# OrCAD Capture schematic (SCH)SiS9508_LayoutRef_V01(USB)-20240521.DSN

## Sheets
1 00_History: title: History; rev: V0.1; note: SiS9508_AP_V01
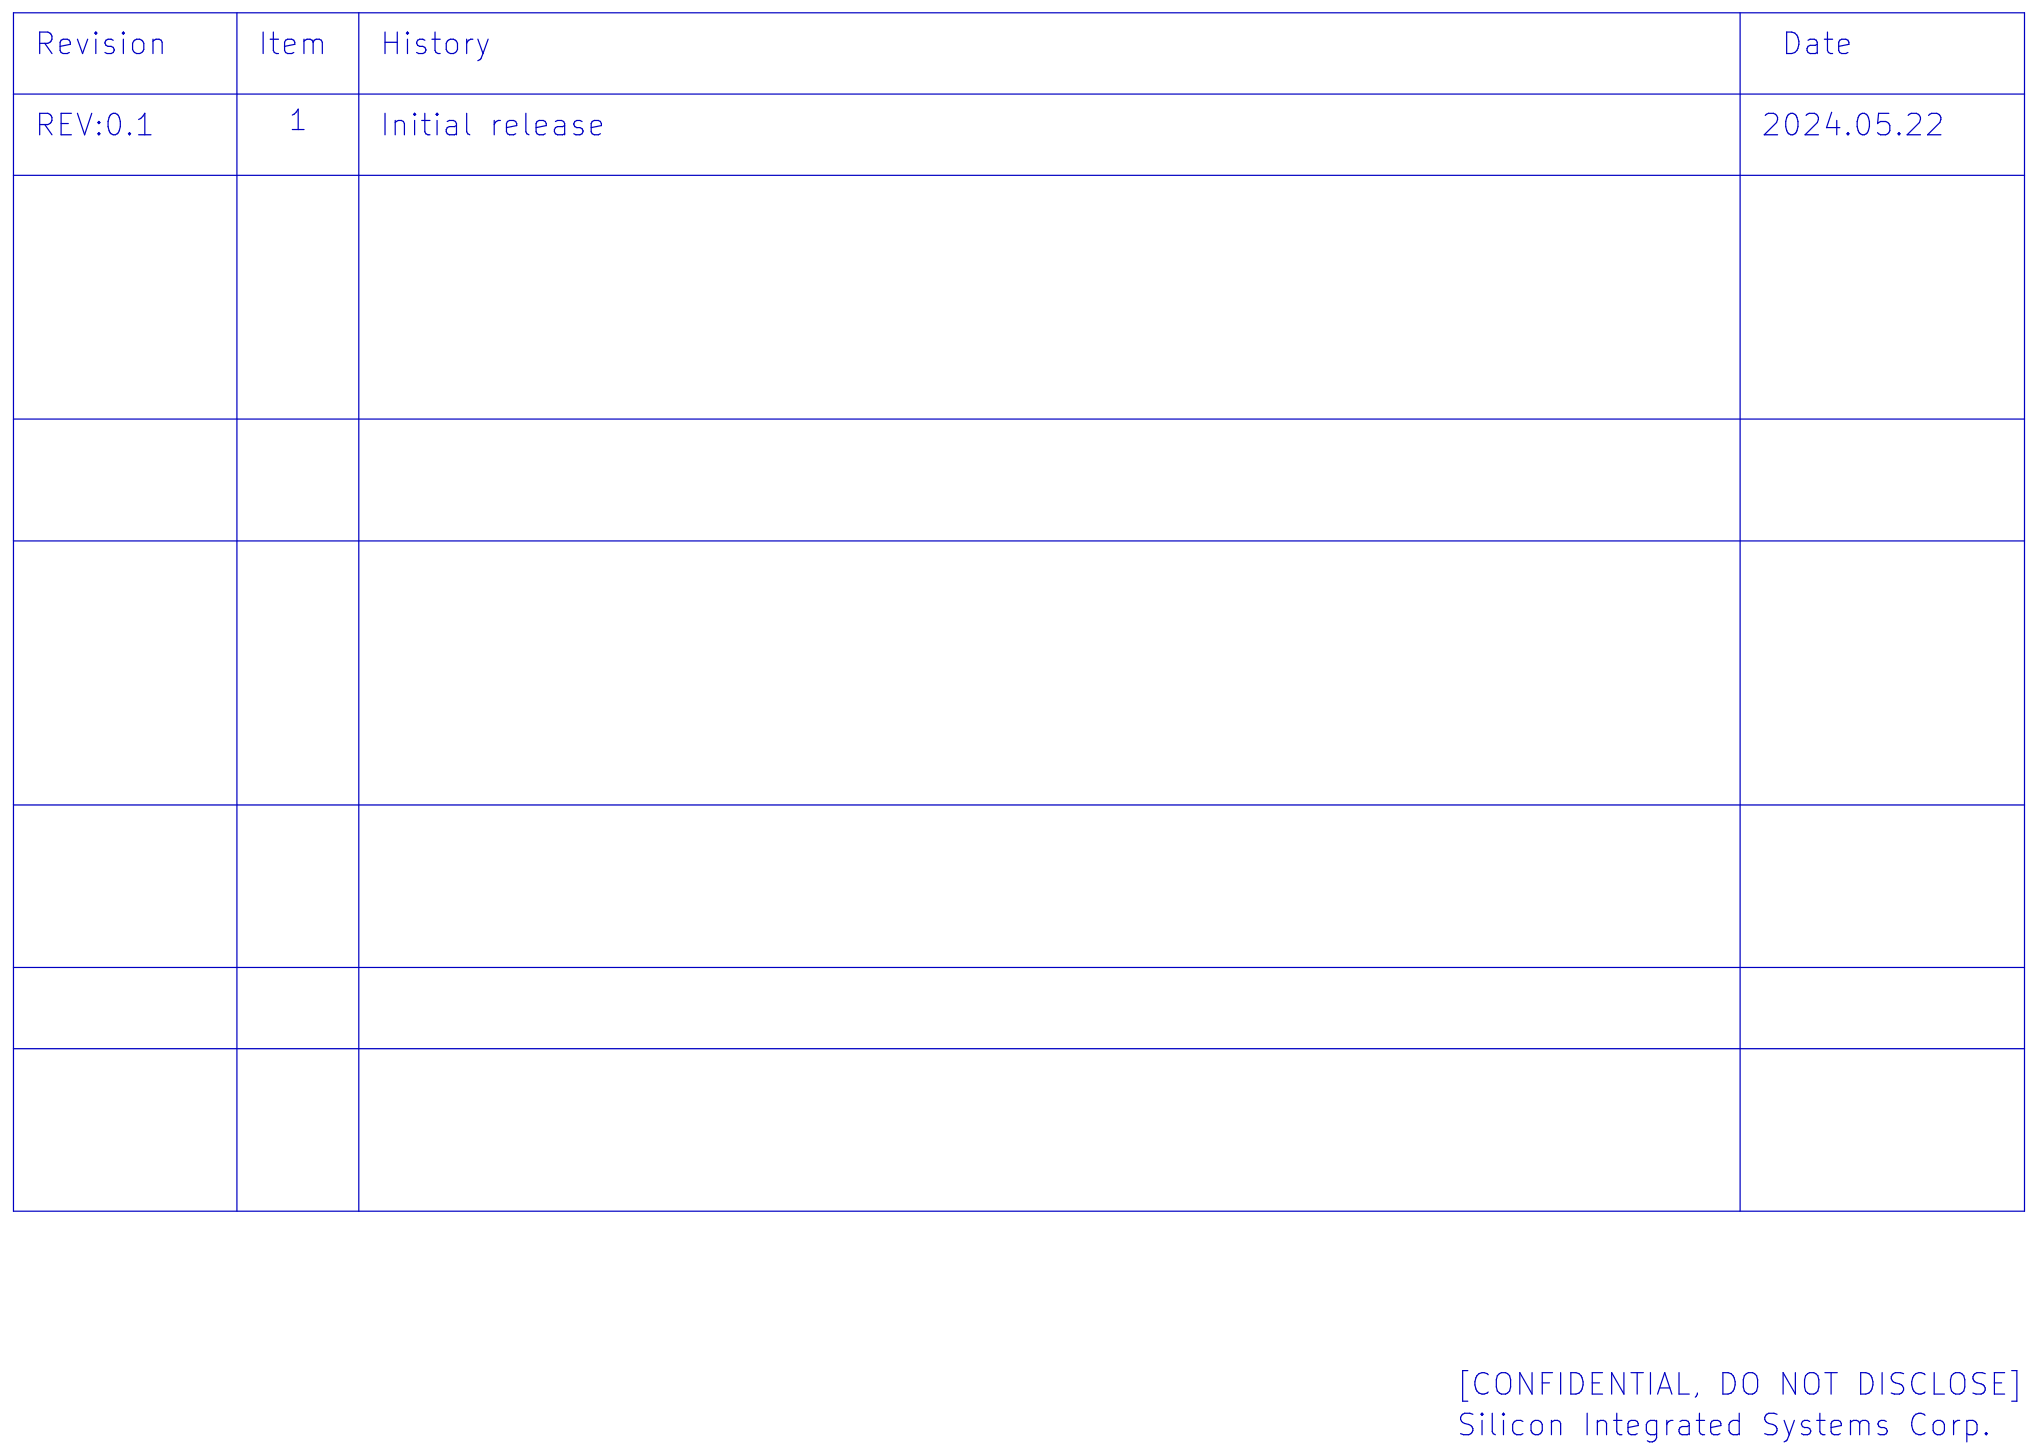
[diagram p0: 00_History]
2 01_SiS9508 - USB: size Custom; title: SiS9508; note: USB interface
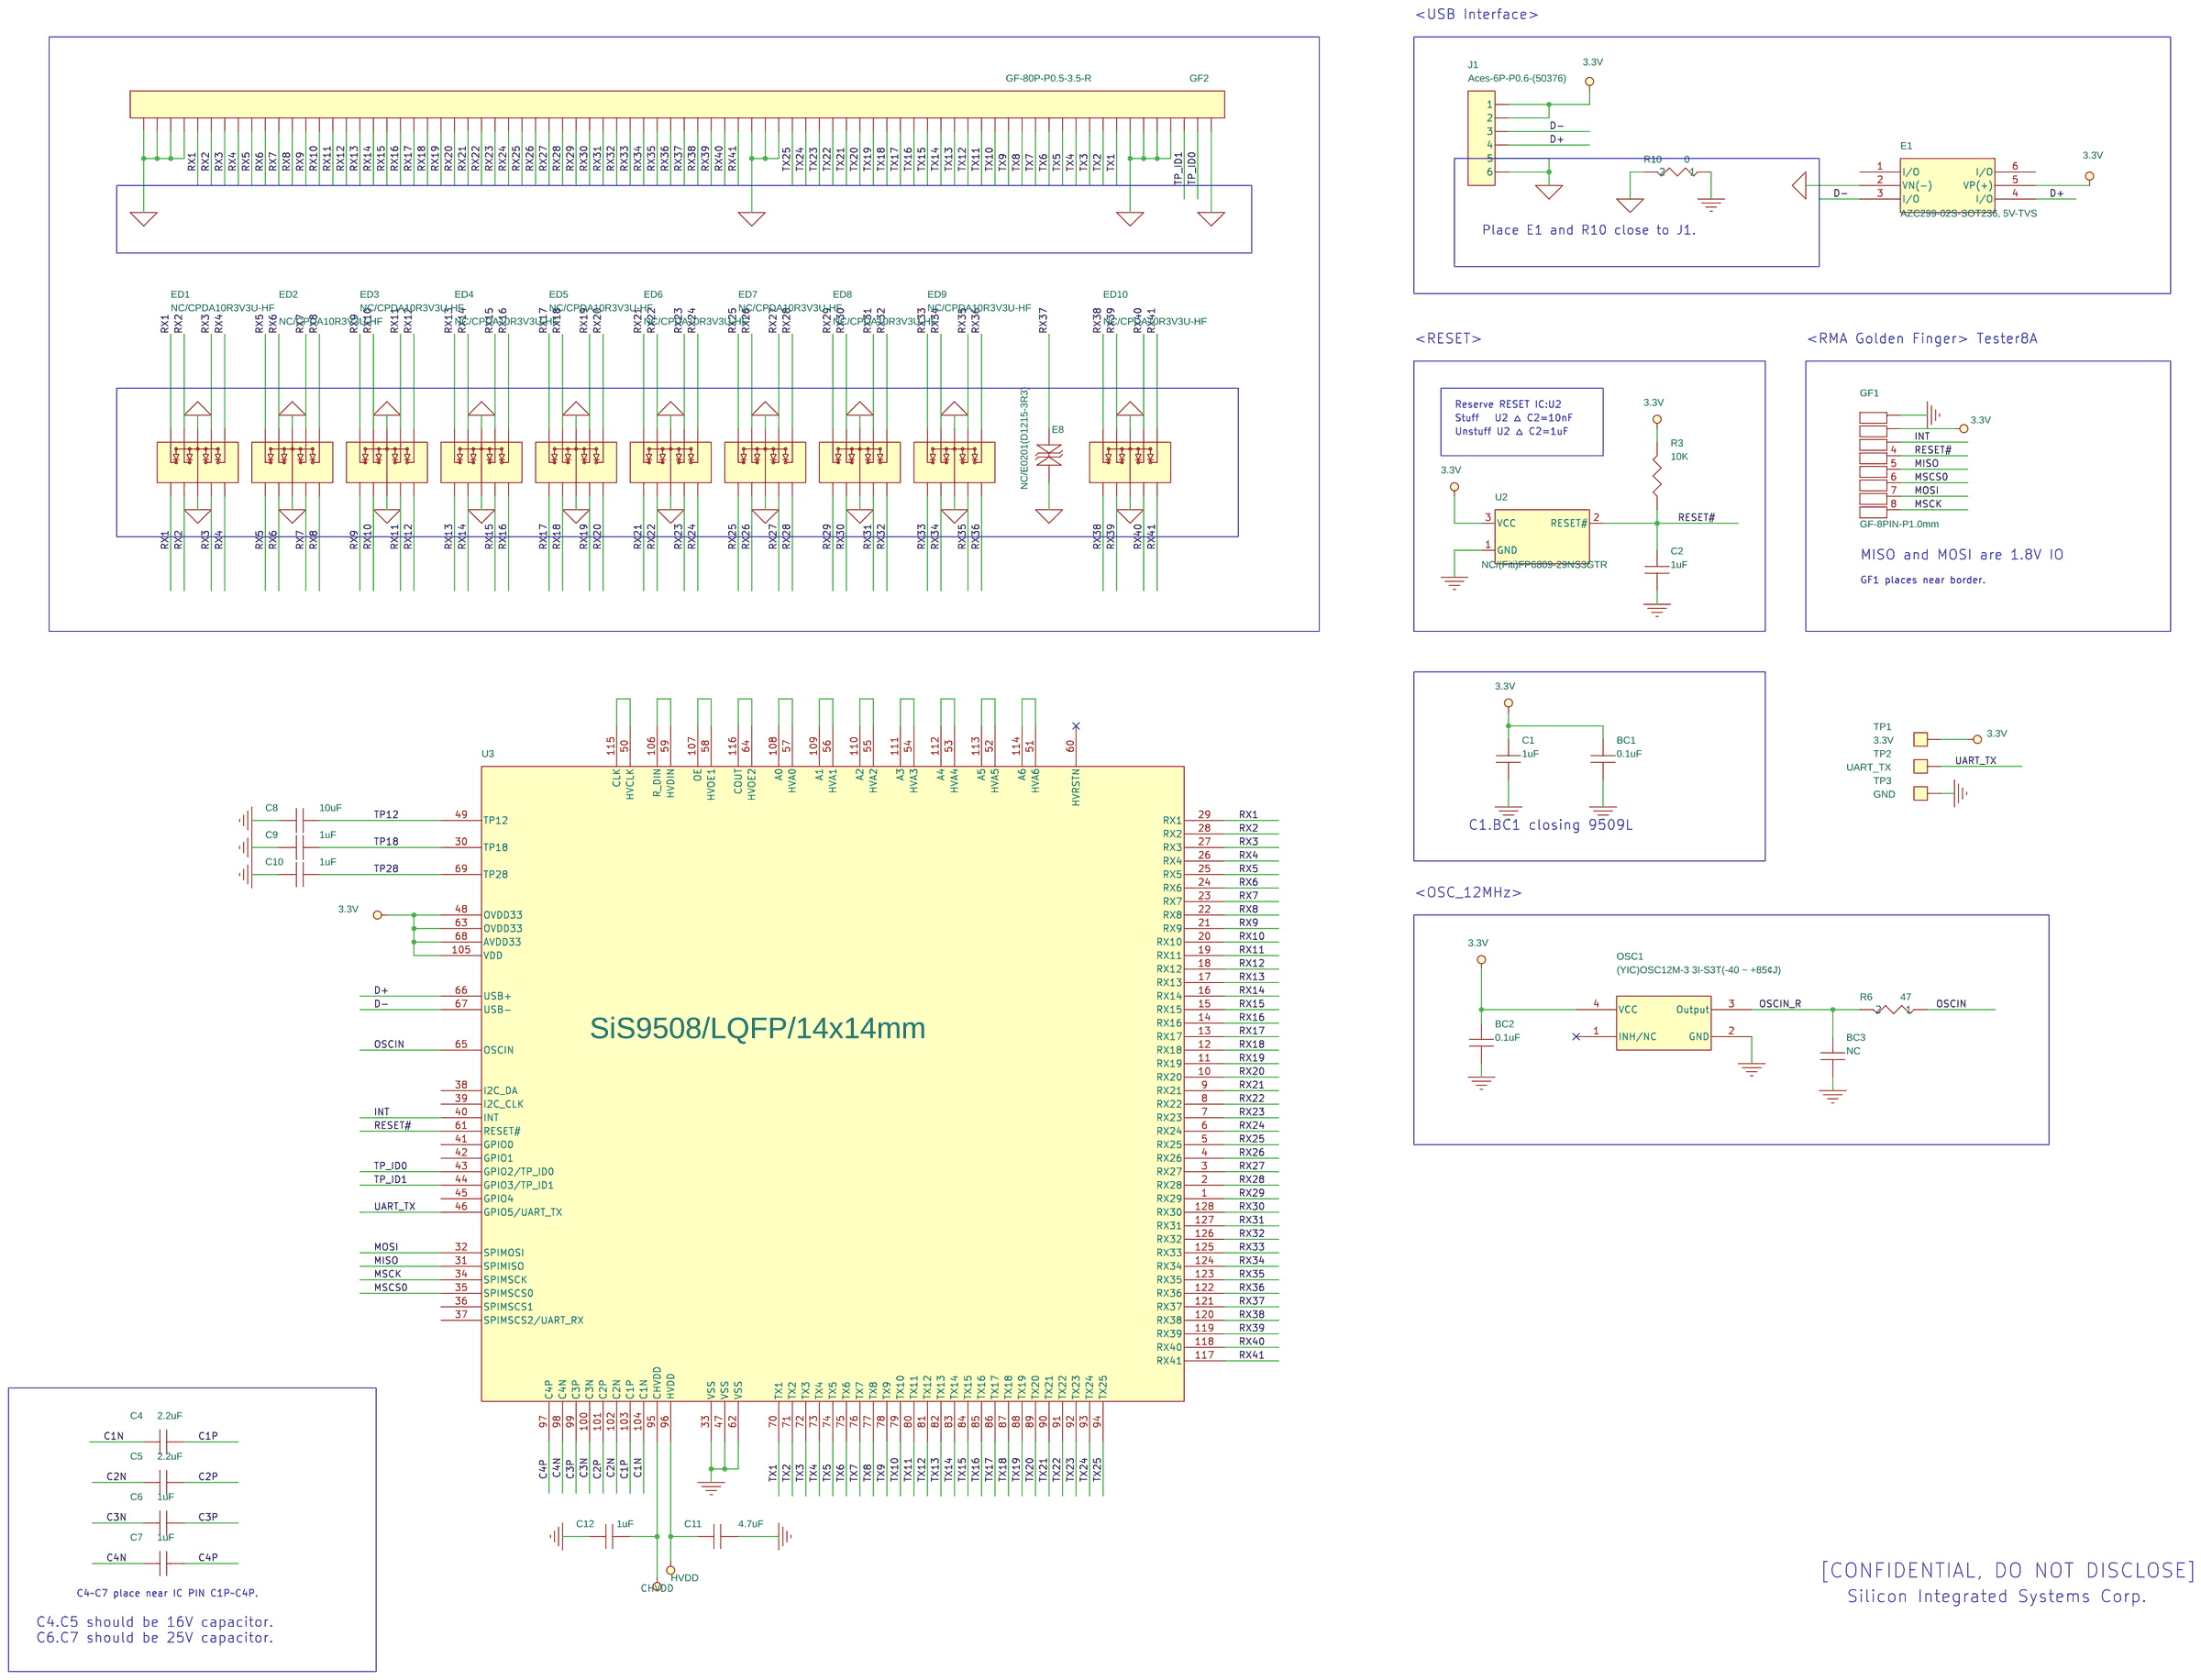
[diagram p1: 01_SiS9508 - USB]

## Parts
BC1  0.1uF  [C0402]
BC2  0.1uF  [C0402]
BC3  NC  [C0402]
C1  1uF  [C0402]
C2  1uF  [C0402]
C4  2.2uF  [C0402]
C5  2.2uF  [C0402]
C6  1uF  [C0402]
C7  1uF  [C0402]
C8  10uF  [C0402]
C9  1uF  [C0402]
C10  1uF  [C0402]
C11  4.7uF  [C0603]
C12  1uF  [C0402]
E1  AZC299-02S-SOT236, 5V-TVS  [E-SOT236L]
E8  NC/E0201(D1215-3R3)  [E0402]
ED1  NC/CPDA10R3V3U-HF  [E-CPDA10R3V3U-HF]
ED2  NC/CPDA10R3V3U-HF  [E-CPDA10R3V3U-HF]
ED3  NC/CPDA10R3V3U-HF  [E-CPDA10R3V3U-HF]
ED4  NC/CPDA10R3V3U-HF  [E-CPDA10R3V3U-HF]
ED5  NC/CPDA10R3V3U-HF  [E-CPDA10R3V3U-HF]
ED6  NC/CPDA10R3V3U-HF  [E-CPDA10R3V3U-HF]
ED7  NC/CPDA10R3V3U-HF  [E-CPDA10R3V3U-HF]
ED8  NC/CPDA10R3V3U-HF  [E-CPDA10R3V3U-HF]
ED9  NC/CPDA10R3V3U-HF  [E-CPDA10R3V3U-HF]
ED10  NC/CPDA10R3V3U-HF  [E-CPDA10R3V3U-HF]
GF1  GF-8PIN-P1.0mm  [GF-8-1.0-1.2]
GF2  GF-80P-P0.5-3.5-R  [GF-80P-P0.5-3.5-R]
J1  Aces-6P-P0.6-(50376)  [CON-6P-P0.6-0.8(50376)]
OSC1  (YIC)OSC12M-3 3I-S3T(-40 ~ +85¢J)  [OSC-4P-SCO-F391]
R3  10K  [R0402]
R6  47  [R0402]
R10  0  [R0402]
TP1  3.3V  [TP1.2]
TP2  UART_TX  [TP1.2]
TP3  GND  [TP1.2]
U2  NC/(Fiti)FP6809-29NS3GTR  [SOT-23/SC-70-3]
U3  SiS9508/LQFP/14x14mm  [(9508)LQFP128P-P0.4-1414-SOCKET.]

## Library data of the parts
BC1-BC3 C1 C2 C8-C10 C12 = C-NP_(C0402_6.3V)
C4-C7 C11 = CAP_NP
E1 = AME8822AEET330Z_(SOT23)_2
E8 = C-NP_(C0402_6_0.3V)
ED1-ED10 = ESD_3: Geometry.Height: 0.55mm
GF1 = GFinger-12P_(GF-12-0.5-2_0.0)
GF2 = CON-80P-P0.5(TF06L_50520_106C)
J1 = CON-5P-P2-3_0.3(DF3DZ-5P-2H)
OSC1 = OSC813500-SCO-F39_0
R3 = R_(R0402)
R6 = R
R10 = R_1
TP1-TP3 = TESTPOINT-SURFACE
U2 = AME8822AEET330Z_(SOT-23)_0
U3 = (9508B)LQFP128P-P0.4-1414

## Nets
3.3V: BC1.1 BC2.1 C1.1 E1.5(VP(+)) GF1.2 J1.1 J1.2 OSC1.4(VCC) R3.2 TP1.1 U2.3(VCC) U3.48(OVDD33) U3.63(OVDD33) U3.68(AVDD33) U3.105(VDD)
DGND: BC1.2 BC2.2 BC3.2 C1.2 C2.2 C8.2 C9.2 C10.2 C11.2 C12.1 GF1.1 OSC1.2(GND) R10.1 TP3.1 U2.1(GND) U3.33(VSS) U3.47(VSS) U3.62(VSS)
GND_SIGNAL: E1.2(VN(-)) E8.2 ED1.3 ED1.8 ED2.3 ED2.8 ED3.3 ED3.8 ED4.3 ED4.8 ED5.3 ED5.8 ED6.3 ED6.8 ED7.3 ED7.8 ED8.3 ED8.8 ED9.3 ED9.8 ED10.3 ED10.8 GF2.1 GF2.4 GF2.5 GF2.6 GF2.7 GF2.33 GF2.34 GF2.35 GF2.77 GF2.78 GF2.79 GF2.80 J1.5 J1.6 R10.2
C1N: C4.1 U3.104(C1N)
C1P: C4.2 U3.103(C1P)
C2N: C5.1 U3.102(C2N)
C2P: C5.2 U3.101(C2P)
C3N: C6.1 U3.100(C3N)
C3P: C6.2 U3.99(C3P)
C4N: C7.1 U3.98(C4N)
C4P: C7.2 U3.97(C4P)
CHVDD: C12.2 U3.95(CHVDD)
D+: E1.4(I/O) J1.4 U3.66(USB+)
D-: E1.3(I/O) J1.3 U3.67(USB-)
HVDD: C11.1 U3.96(HVDD)
INT: GF1.3 U3.40(INT)
MISO: GF1.5 U3.31(SPIMISO)
MOSI: GF1.7 U3.32(SPIMOSI)
MSCK: GF1.8 U3.34(SPIMSCK)
MSCS0: GF1.6 U3.35(SPIMSCS0)
OSCIN: R6.1 U3.65(OSCIN)
OSCIN_R: BC3.1 OSC1.3(Output) R6.2
RESET#: C2.1 GF1.4 R3.1 U2.2(RESET#) U3.61(RESET#)
RX1: ED1.5 ED1.6 GF2.76 U3.29(RX1)
RX2: ED1.4 ED1.7 GF2.75 U3.28(RX2)
RX3: ED1.2 ED1.9 GF2.74 U3.27(RX3)
RX4: ED1.1 ED1.10 GF2.73 U3.26(RX4)
RX5: ED2.5 ED2.6 GF2.72 U3.25(RX5)
RX6: ED2.4 ED2.7 GF2.71 U3.24(RX6)
RX7: ED2.2 ED2.9 GF2.70 U3.23(RX7)
RX8: ED2.1 ED2.10 GF2.69 U3.22(RX8)
RX9: ED3.5 ED3.6 GF2.68 U3.21(RX9)
RX10: ED3.4 ED3.7 GF2.67 U3.20(RX10)
RX11: ED3.2 ED3.9 GF2.66 U3.19(RX11)
RX12: ED3.1 ED3.10 GF2.65 U3.18(RX12)
RX13: ED4.5 ED4.6 GF2.64 U3.17(RX13)
RX14: ED4.4 ED4.7 GF2.63 U3.16(RX14)
RX15: ED4.2 ED4.9 GF2.62 U3.15(RX15)
RX16: ED4.1 ED4.10 GF2.61 U3.14(RX16)
RX17: ED5.5 ED5.6 GF2.60 U3.13(RX17)
RX18: ED5.4 ED5.7 GF2.59 U3.12(RX18)
RX19: ED5.2 ED5.9 GF2.58 U3.11(RX19)
RX20: ED5.1 ED5.10 GF2.57 U3.10(RX20)
RX21: ED6.5 ED6.6 GF2.56 U3.9(RX21)
RX22: ED6.4 ED6.7 GF2.55 U3.8(RX22)
RX23: ED6.2 ED6.9 GF2.54 U3.7(RX23)
RX24: ED6.1 ED6.10 GF2.53 U3.6(RX24)
RX25: ED7.5 ED7.6 GF2.52 U3.5(RX25)
RX26: ED7.4 ED7.7 GF2.51 U3.4(RX26)
RX27: ED7.2 ED7.9 GF2.50 U3.3(RX27)
RX28: ED7.1 ED7.10 GF2.49 U3.2(RX28)
RX29: ED8.5 ED8.6 GF2.48 U3.1(RX29)
RX30: ED8.4 ED8.7 GF2.47 U3.128(RX30)
RX31: ED8.2 ED8.9 GF2.46 U3.127(RX31)
RX32: ED8.1 ED8.10 GF2.45 U3.126(RX32)
RX33: ED9.5 ED9.6 GF2.44 U3.125(RX33)
RX34: ED9.4 ED9.7 GF2.43 U3.124(RX34)
RX35: ED9.2 ED9.9 GF2.42 U3.123(RX35)
RX36: ED9.1 ED9.10 GF2.41 U3.122(RX36)
RX37: E8.1 GF2.40 U3.121(RX37)
RX38: ED10.5 ED10.6 GF2.39 U3.120(RX38)
RX39: ED10.4 ED10.7 GF2.38 U3.119(RX39)
RX40: ED10.2 ED10.9 GF2.37 U3.118(RX40)
RX41: ED10.1 ED10.10 GF2.36 U3.117(RX41)
TP12: C8.1 U3.49(TP12)
TP18: C9.1 U3.30(TP18)
TP28: C10.1 U3.69(TP28)
TP_ID0: GF2.2 U3.43(GPIO2/TP_ID0)
TP_ID1: GF2.3 U3.44(GPIO3/TP_ID1)
TX1: GF2.8 U3.70(TX1)
TX2: GF2.9 U3.71(TX2)
TX3: GF2.10 U3.72(TX3)
TX4: GF2.11 U3.73(TX4)
TX5: GF2.12 U3.74(TX5)
TX6: GF2.13 U3.75(TX6)
TX7: GF2.14 U3.76(TX7)
TX8: GF2.15 U3.77(TX8)
TX9: GF2.16 U3.78(TX9)
TX10: GF2.17 U3.79(TX10)
TX11: GF2.18 U3.80(TX11)
TX12: GF2.19 U3.81(TX12)
TX13: GF2.20 U3.82(TX13)
TX14: GF2.21 U3.83(TX14)
TX15: GF2.22 U3.84(TX15)
TX16: GF2.23 U3.85(TX16)
TX17: GF2.24 U3.86(TX17)
TX18: GF2.25 U3.87(TX18)
TX19: GF2.26 U3.88(TX19)
TX20: GF2.27 U3.89(TX20)
TX21: GF2.28 U3.90(TX21)
TX22: GF2.29 U3.91(TX22)
TX23: GF2.30 U3.92(TX23)
TX24: GF2.31 U3.93(TX24)
TX25: GF2.32 U3.94(TX25)
UART_TX: TP2.1 U3.46(GPIO5/UART_TX)
N20133298: U3.50(HVCLK) U3.115(CLK)
N20133304: U3.59(HVDIN) U3.106(R_DIN)
N20133310: U3.58(HVOE1) U3.107(OE)
N20133316: U3.64(HVOE2) U3.116(COUT)
N20133322: U3.57(HVA0) U3.108(A0)
N20133328: U3.56(HVA1) U3.109(A1)
N20133334: U3.55(HVA2) U3.110(A2)
N20133340: U3.54(HVA3) U3.111(A3)
N20133346: U3.53(HVA4) U3.112(A4)
N20133352: U3.52(HVA5) U3.113(A5)
N20133358: U3.51(HVA6) U3.114(A6)

Not connected (* = marked no-connect by the designer): E1 1(I/O) 6(I/O); OSC1 1(INH/NC)*; U3 36(SPIMSCS1) 37(SPIMSCS2/UART_RX) 38(I2C_DA) 39(I2C_CLK) 41(GPIO0) 42(GPIO1) 45(GPIO4) 60(HVRSTN)*

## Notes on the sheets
sheet 1
- Revision
- Item
- History
- Date
- REV:0.1
- 1
- Initial release
- 2024.05.22
- [CONFIDENTIAL, DO NOT DISCLOSE]
- Silicon Integrated Systems Corp.
sheet 2
- <USB Interface>
- Place E1 and R10 close to J1.
- <RESET>
- <RMA Golden Finger> Tester8A
- Reserve RESET IC:U2
- Stuff   U2 △ C2=10nF
- Unstuff U2 △ C2=1uF
- MISO and MOSI are 1.8V IO
- GF1 places near border.
- C1.BC1 closing 9509L
- <OSC_12MHz>
- [CONFIDENTIAL, DO NOT DISCLOSE]
- C4~C7 place near IC PIN C1P~C4P.
- Silicon Integrated Systems Corp.
- C4.C5 should be 16V capacitor.
  C6.C7 should be 25V capacitor.
